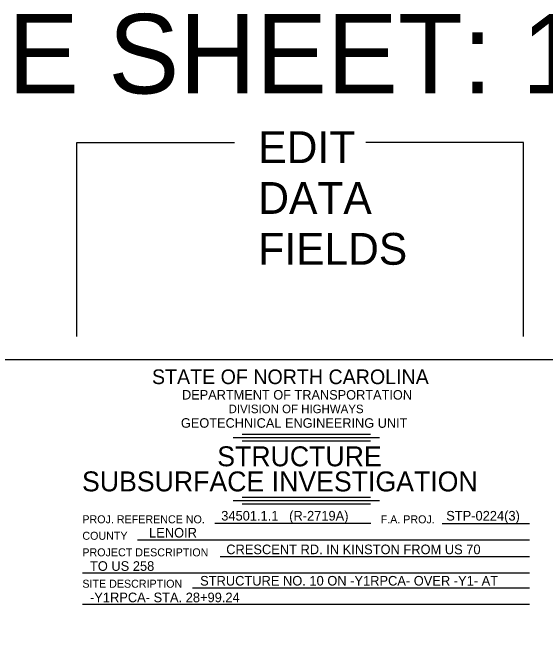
# Model space of a CAD drawing. Extents: x 278710 to 279187, y 171464 to 171625.
# Drawn here: x 278796.7 to 278863.6, y 171543.9 to 171624.6 of the extents above; entities that cross this region are included whole.
import ezdxf

# ---------------------------------------------------------------- set-up
doc = ezdxf.new("R2010")
doc.units = 0
doc.layers.add('Geotech Sheets and Borders Cell', color=7, linetype='Continuous')
doc.layers.add('Prop Strc Sect_ Misc - User Comment (Tx - small)', color=7, linetype='Continuous')

msp = doc.modelspace()

# ---------------------------------------------------------------- linework, layer by layer
at = {"layer": 'Geotech Sheets and Borders Cell'}
for p, q in [((278825.512, 171571.572), (278841.686, 171571.572)), ((278824.376, 171571.14), (278842.821, 171571.14)), ((278825.512, 171570.709), (278841.686, 171570.709)), ((278824.376, 171563.208), (278842.821, 171563.208)), ((278825.512, 171563.64), (278841.686, 171563.64)), ((278825.512, 171562.777), (278841.686, 171562.777)), ((278822.088, 171560.345), (278841.704, 171560.345)), ((278850.671, 171560.339), (278861.686, 171560.339)), ((278812.347, 171558.272), (278861.686, 171558.272)), ((278822.769, 171556.186), (278861.686, 171556.186)), ((278805.427, 171554.104), (278861.686, 171554.104)), ((278819.279, 171552.237), (278861.687, 171552.237)), ((278805.428, 171550.155), (278861.687, 171550.155))]:
    msp.add_line(p, q, dxfattribs=at)
for points in [[(278804.734, 171583.842), (278804.734, 171608.273), (278824.55, 171608.273)], [(278860.915, 171583.842), (278860.915, 171608.273), (278841.099, 171608.273)]]:
    msp.add_lwpolyline(points, dxfattribs=at)
msp.add_lwpolyline([(278756.087, 171580.949), (278907.338, 171580.949), (278907.338, 171476.081), (278756.087, 171476.081)], close=True, dxfattribs=at)

# ---------------------------------------------------------------- texts
for s, height, p in [('EDIT', 4, (278827.56, 171605.683)), ('DATA', 4, (278827.56, 171599.283)), ('FIELDS', 4, (278827.56, 171592.883)), ('34501.1.1   (R-2719A)', 1.2096, (278822.894, 171560.69)), ('STP-0224(3)', 1.2096, (278851.195, 171560.69)), ('LENOIR', 1.2096, (278813.819, 171558.552)), ('CRESCENT RD. IN KINSTON FROM US 70 ', 1.2096, (278823.521, 171556.456)), ('TO US 258', 1.2096, (278806.382, 171554.36)), ('STRUCTURE NO. 10 ON -Y1RPCA- OVER -Y1- AT  ', 1.2096, (278820.239, 171552.507)), ('-Y1RPCA- STA. 28+99.24', 1.2096, (278806.383, 171550.411))]:
    msp.add_text(s, height=height, dxfattribs=at).set_placement(p)
for s, height, p in [('STATE OF NORTH CAROLINA', 1.84505, (278814.181, 171577.863)), ('DEPARTMENT OF TRANSPORTATION', 1.19808, (278817.959, 171575.918)), ('DIVISION OF HIGHWAYS', 1.07827, (278823.816, 171574.203)), ('GEOTECHNICAL ENGINEERING UNIT', 1.19808, (278817.824, 171572.371)), ('STRUCTURE', 2.5088, (278822.392, 171567.52)), ('SUBSURFACE INVESTIGATION', 2.5088, (278805.379, 171564.365)), ('PROJ. REFERENCE NO.', 1.00637, (278805.426, 171560.346)), ('F.A. PROJ.', 1.0064, (278842.947, 171560.341)), ('COUNTY', 1.0064, (278805.425, 171558.272)), ('PROJECT DESCRIPTION', 1.00637, (278805.424, 171556.188)), ('SITE DESCRIPTION', 1.00637, (278805.425, 171552.239))]:
    msp.add_text(s, height=height, rotation=359.98728, dxfattribs=at).set_placement(p)
at = {"layer": 'Prop Strc Sect_ Misc - User Comment (Tx - small)'}
msp.add_text('TITLE SHEET: 11" x 17"', height=10, dxfattribs=at).set_placement((278768.566, 171614.437))

doc.saveas('drawing.dxf')
